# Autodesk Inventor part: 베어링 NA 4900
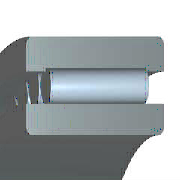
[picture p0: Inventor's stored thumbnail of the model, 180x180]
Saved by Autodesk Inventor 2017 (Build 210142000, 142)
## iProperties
Created: 2021-07
Part Number: 베어링 NA 4900
Material: 강철, 연강
Description: 니들 롤러 베어링 - 경계 치수 및 공차
Document SubType Name: Modeling
Standard: KS B 2029
Designer: mdu
Standards Organization: KS
Language: ko-KR
Size Designation: NA 4900 - 10 x 22 x 13
Categories: <MemberInstance><Categories><Category DisplayName="샤프트 부품" InternalName="7f7aeb1f-a693-4053-b835-cee3144e0d98" Mnemonic="SHFT"><Category DisplayName="베어링" Inter
Density: 7.86 g/cm^3
Mass: 23.8213 g
Surface Area: 38.613 cm^2
Volume: 3.0307 cm^3
Appearance: 베이지색
IsCustomPart: 0
Author: mdu
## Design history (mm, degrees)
sketch "스케치"
  geometry: L1 (1.857, 9)-(11.143, 9); L2 (11.143, 9)-(11.143, 7); L3 (13, 7)-(0, 7); L4 (1.857, 7)-(1.857, 9); L5 (1.857, 8)-(11.143, 8); L6 (6.5, 8)-(6.5, 7); L7 (0, 5)-(13, 5); L8 (0, 11)-(13, 11); L9 (13, 5)-(13, 7); L10 (13, 8.8)-(13, 11); L11 (1.857, 8.8)-(0, 8.8); L12 (11.143, 8.8)-(13, 8.8); L13 (-6, 0)-(36, 0) reference; L14 (0, -1.9)-(0, 14.9) reference
  constraints: 24 end point, 8 point on line, 3 midpoint, 3 parallel, 3 perpendicular, 2 symmetric about line, 1 horizontal, 1 other
  dimensions: "d6" = 10 diameter of L7 L13 (= WD); "d7" = 14 diameter of L3 L13 (= KID1); "d8" = 22 diameter of L8 L13 (= BD); "d9" = 16 diameter of L6.start L13 (= 0.5 x WD + 0.5 x BD); "d10" = 17.6 diameter of L12 L13 (= 0.9 x BD + 0.9 x WD - 0.8 x KID1); "d11" = 18 diameter of L1 L13 (= BD + WD - KID1); "d12" = 1.85714 distance between parallel lines of L14 L4 (= 0.142857 x KB); "d13" = 13 distance between parallel lines of L14 L9 (= KB); "d14" = 11.14286 distance between parallel lines of L14 L2 (= 0.857143 x KB)
revolve "본체" stored, may be unused: angle "d17" = 90 deg
revolve "롤러" stored, may be unused: angle "d18" = 90 deg
pattern_circular "IDS_ARRAYROLLER[SIMPL:T]" dims angle "d2" = 360 deg
body "Solid1"
fillet "모깎기1" dims "d0" = 0.3 (= KRS)
other parameters: "WD" = 10 [user parameter; used in 6 equation terms], "BD" = 22 [user parameter; used in 6 equation terms], "KB" = 13 [user parameter; used in 3 equation terms], "KID1" = 14 [user parameter; used in 4 equation terms], "KRS" = 0.3 [user parameter; used in 1 equation term], "d3" = 0, "d4" = 0, "d5" = 0, "d15" = 0, "d16" = 0, "BC0" = 9150000 [user parameter], "WR" = 5 (= 0.5 x WD) [user parameter], "BBA" = 0 [user parameter], "BC" = 8150000 [user parameter], "BR" = 11 (= 0.5 x BD) [user parameter]
